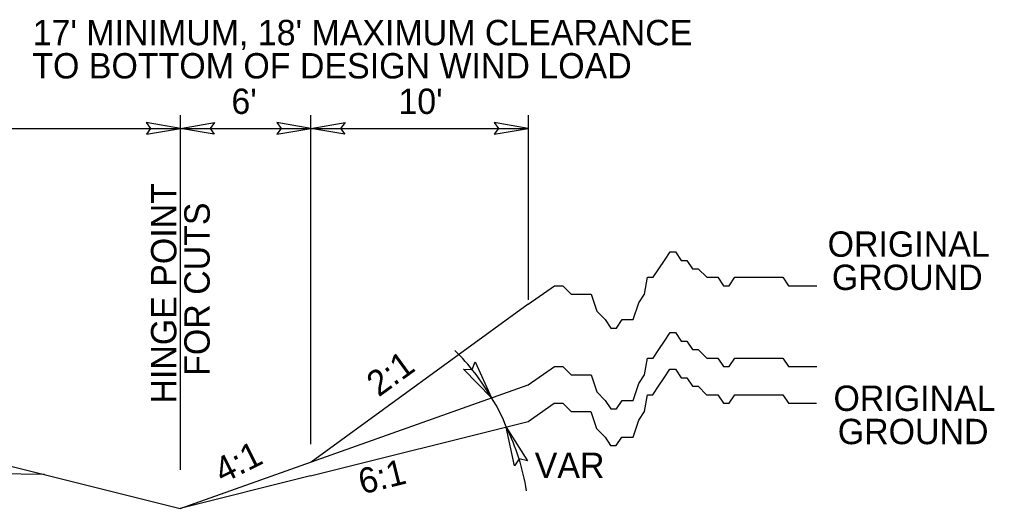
# Model space of a CAD drawing. Extents: x 1726790 to 1728895, y 539219 to 541550.
# Drawn here: x 1727891.1 to 1728160.3, y 541295.4 to 541430.6 of the extents above; entities that cross this region are included whole.
import ezdxf

# ---------------------------------------------------------------- set-up
doc = ezdxf.new("R2010")
doc.units = 0
for name, color, linetype in [('Default', 7, 'Continuous'), ('Prop Dimension Text', 7, 'Continuous'), ('Typical Hinge Slope Interstate CELL', 7, 'Continuous'), ('Typical Pavement Slope CELL', 7, 'Continuous')]:
    doc.layers.add(name, color=color, linetype=linetype)

msp = doc.modelspace()

# ---------------------------------------------------------------- linework, layer by layer
at = {"layer": 'Default'}
for p, q in [((1727935.5, 541306.16), (1727935.5, 541404.16)), ((1727971.53, 541313.2), (1727971.53, 541404.16)), ((1728031.58, 541353.09), (1728031.58, 541404.16)), ((1727827.38, 541400.46), (1727935.46, 541400.46)), ((1727935.46, 541400.46), (1727971.49, 541400.46)), ((1727971.49, 541400.46), (1728031.54, 541400.46))]:
    msp.add_line(p, q, dxfattribs=at)
for points in [[(1727926.12, 541398.85), (1727935.5, 541400.47), (1727926.07, 541402.14), (1727927.27, 541400.47)], [(1727944.88, 541398.85), (1727935.5, 541400.47), (1727944.93, 541402.14), (1727943.73, 541400.47)], [(1727962.15, 541398.85), (1727971.53, 541400.47), (1727962.1, 541402.14), (1727963.3, 541400.47)], [(1727980.91, 541398.85), (1727971.53, 541400.47), (1727980.96, 541402.14), (1727979.76, 541400.47)], [(1728022.16, 541398.85), (1728031.54, 541400.46), (1728022.11, 541402.13), (1728023.31, 541400.46)], [(1728016.86, 541335.98), (1728021.41, 541326), (1728013.7, 541333.9), (1728016.07, 541333.84)], [(1728027.78, 541307.25), (1728025.45, 541317.96), (1728031.31, 541308.61), (1728029.01, 541309.17)], [(1728027.78, 541307.25), (1728025.45, 541317.96), (1728031.31, 541308.61), (1728029.01, 541309.17)]]:
    msp.add_lwpolyline(points, close=True, dxfattribs=at)
at = {"layer": 'Typical Hinge Slope Interstate CELL'}
for points in [[(1728031.54, 541351.91), (1728038.76, 541356.98), (1728041.1, 541356.98), (1728043.43, 541354.65), (1728044.99, 541354.65), (1728047.33, 541354.65), (1728048.88, 541354.65), (1728050.44, 541349.96), (1728052.78, 541347.64), (1728054.34, 541345.29), (1728055.89, 541345.29), (1728057.45, 541347.64), (1728059.01, 541347.64), (1728060.56, 541347.64), (1728062.12, 541352.31), (1728063.68, 541354.65), (1728064.46, 541359.32), (1728066.02, 541359.32), (1728067.58, 541361.65), (1728069.13, 541364), (1728070.69, 541366.34), (1728072.25, 541366.34), (1728073.8, 541364), (1728075.36, 541364), (1728076.92, 541361.65), (1728078.48, 541361.65), (1728080.82, 541359.32), (1728082.37, 541359.32), (1728083.93, 541359.32), (1728085.49, 541356.98), (1728087.04, 541356.98), (1728088.6, 541359.32), (1728090.16, 541359.32), (1728091.72, 541359.32), (1728093.27, 541359.32), (1728094.83, 541359.32), (1728097.17, 541359.32), (1728099.5, 541359.32), (1728101.84, 541359.32), (1728103.4, 541356.98), (1728105.73, 541356.98), (1728108.07, 541356.98), (1728111.18, 541356.98)], [(1728031.54, 541329.6), (1728038.76, 541334.67), (1728041.1, 541334.67), (1728043.43, 541332.34), (1728044.99, 541332.34), (1728047.33, 541332.34), (1728048.88, 541332.34), (1728050.44, 541327.65), (1728052.78, 541325.32), (1728054.34, 541322.98), (1728055.89, 541322.98), (1728057.45, 541325.32), (1728059.01, 541325.32), (1728060.56, 541325.32), (1728062.12, 541330), (1728063.68, 541332.34), (1728064.46, 541337.01), (1728066.02, 541337.01), (1728067.58, 541339.34), (1728069.13, 541341.68), (1728070.69, 541344.03), (1728072.25, 541344.03), (1728073.8, 541341.68), (1728075.36, 541341.68), (1728076.92, 541339.34), (1728078.48, 541339.34), (1728080.82, 541337.01), (1728082.37, 541337.01), (1728083.93, 541337.01), (1728085.49, 541334.67), (1728087.04, 541334.67), (1728088.6, 541337.01), (1728090.16, 541337.01), (1728091.72, 541337.01), (1728093.27, 541337.01), (1728094.83, 541337.01), (1728097.17, 541337.01), (1728099.5, 541337.01), (1728101.84, 541337.01), (1728103.4, 541334.67), (1728105.73, 541334.67), (1728108.07, 541334.67), (1728111.18, 541334.67)], [(1728031.51, 541319.48), (1728038.72, 541324.54), (1728041.06, 541324.54), (1728043.4, 541322.22), (1728044.95, 541322.22), (1728047.29, 541322.22), (1728048.85, 541322.22), (1728050.41, 541317.53), (1728052.75, 541315.2), (1728054.3, 541312.86), (1728055.86, 541312.86), (1728057.42, 541315.2), (1728058.98, 541315.2), (1728060.53, 541315.2), (1728062.09, 541319.87), (1728063.65, 541322.22), (1728064.43, 541326.89), (1728065.99, 541326.89), (1728067.54, 541329.22), (1728069.1, 541331.56), (1728070.66, 541333.91), (1728072.21, 541333.91), (1728073.77, 541331.56), (1728075.33, 541331.56), (1728076.89, 541329.22), (1728078.44, 541329.22), (1728080.78, 541326.89), (1728082.34, 541326.89), (1728083.9, 541326.89), (1728085.45, 541324.54), (1728087.01, 541324.54), (1728088.57, 541326.89), (1728090.13, 541326.89), (1728091.68, 541326.89), (1728093.24, 541326.89), (1728094.8, 541326.89), (1728097.14, 541326.89), (1728099.47, 541326.89), (1728101.81, 541326.89), (1728103.37, 541324.54), (1728105.7, 541324.54), (1728108.04, 541324.54), (1728111.15, 541324.54)]]:
    msp.add_lwpolyline(points, dxfattribs=at)
for centre, start, end in [((1727969.01, 541296.05), 29.7519, 45.5036), ((1727971.47, 541290.97), 8.9538, 26.5701), ((1727971.47, 541290.97), 8.9538, 26.5701)]:
    msp.add_arc(centre, 60.35, start, end, dxfattribs=at)
msp.add_ellipse((1727970.92, 541329.03), major_axis=(54.47, -25.99), ratio=0.5, start_param=0.463735, end_param=0.681536, dxfattribs=at)
at = {"layer": 'Typical Pavement Slope CELL'}
for p, q in [((1728031.54, 541351.91), (1727971.57, 541308.29)), ((1727935.45, 541295.46), (1728031.54, 541329.6)), ((1727827.39, 541322.46), (1727935.46, 541295.44)), ((1727971.47, 541304.47), (1728031.51, 541319.48)), ((1727898, 541304.81), (1727695.28, 541308.86)), ((1727971.47, 541304.47), (1727935.45, 541295.46))]:
    msp.add_line(p, q, dxfattribs=at)

# ---------------------------------------------------------------- texts
at = {"layer": 'Prop Dimension Text'}
for s, height, p in [("17' MINIMUM, 18' MAXIMUM CLEARANCE", 7.0055, (1727894.73, 541423.45)), ('TO BOTTOM OF DESIGN WIND LOAD', 7.0055, (1727894.62, 541414.27)), ("6'", 7.005, (1727949.6, 541404.46)), ("10'", 7.005, (1727995.7, 541404.46)), ('ORIGINAL', 7.005, (1728114.2, 541365)), ('GROUND', 7.005, (1728115.38, 541355.82)), ('ORIGINAL', 7.005, (1728115.82, 541322.41)), ('GROUND', 7.005, (1728117, 541313.22)), ('VAR', 7.005, (1728033.34, 541303.86))]:
    msp.add_text(s, height=height, dxfattribs=at).set_placement(p)
for s, height, rotation, p in [('HINGE POINT', 7.0055, 90, (1727934.41, 541324.44)), ('FOR CUTS', 7.005, 90, (1727943.6, 541332.11)), ('2:1', 7.005, 36.0298, (1727990.25, 541326.09)), ('4:1', 7.005, 26.5701, (1727947.17, 541302.25)), ('6:1', 7.005, 14.0381, (1727985.68, 541299.31))]:
    msp.add_text(s, height=height, rotation=rotation, dxfattribs=at).set_placement(p)

doc.saveas('drawing.dxf')
